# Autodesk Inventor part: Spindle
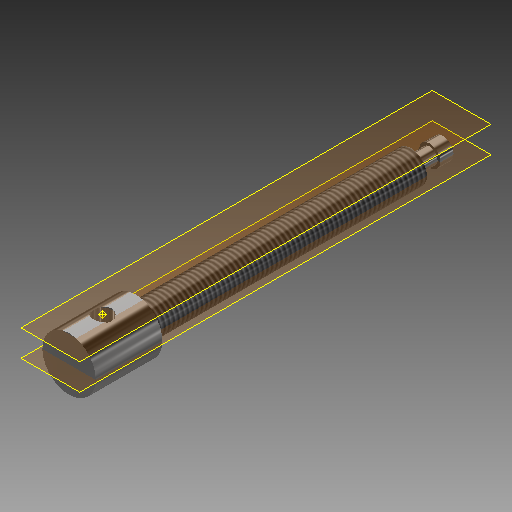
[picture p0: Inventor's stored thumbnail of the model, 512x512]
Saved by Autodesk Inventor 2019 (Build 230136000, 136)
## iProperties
Created: 2011-02
Part Number: Spindle
Material: Generic
Document SubType Name: Modeling
Designer: landrews
Density: 1 g/cm^3
Appearance: Knurled 45
Mass: 19.1947 g
Surface Area: 67.311 cm^2
Volume: 19.1947 cm^3
Author: landrews
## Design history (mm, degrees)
sketch "Sketch1"
  geometry: L1 (3, 5)-(4, 5); L2 (4, 5)-(4, 0); L3 (4, 0)-(0, 0); L4 (6, 115)-(6, 15); L5 (10, 115)-(6, 115); L6 (0, 140)-(10, 140); L7 (10, 140)-(10, 115); L8 (0, 168)-(0, -28) reference; L9 (-2, 0)-(12, 0) reference; L10 (3, 5)-(3, 15); L11 (3, 15)-(6, 15); L12 (0, 140)-(0, 0)
  constraints: 20 end point, 5 parallel, 3 perpendicular, 2 point on line, 1 collinear
  dimensions: "d4" = 25 distance between parallel lines of L6 L5; "d8" = 5 distance between parallel lines of L3 L1; "d9" = 140 distance between parallel lines of L9 L6; "d12" = 15 distance from line of L9 L4.end; "d15" = 12 diameter of L4 L12; "d16" = 6 diameter of L10 L8; "d17" = 8 diameter of L2 L8; "d18" = 20 diameter of L7 L12
revolve "Revolution1" sketch "Sketch1" stored, may be unused: angle "d19" = 90 deg
workplane "Work Plane1"
sketch "Sketch2"
  geometry: L1 (0, -155.5)-(0, 40.5) reference; L2 (-10, 12.5)-(10, 12.5) reference; 2 further points
  constraints: 1 point on line
  dimensions: "d20" = 12.5 distance from line of L2 point (0, 0)
hole "Hole1" sketch "Sketch2" at (0, 0) diameter "d21" = 7; stored, may be unused: countersink angle "d25" = 90 deg, drill point angle "d27" = 118 deg; dims "d22" = 6, "d23" = 4, "d24" = 2, "d26" = 8
thread "Thread1" dims "d28" = 10, "d29" = 0
workplane "Work Plane3"
  workplane "Work Plane2"
node "Direct Edit1"
body "Solid1"
node "Projected Loop1"
workpoint "Work Point1"
move_body "Move1" dims "d35" = 3
other parameters: "d30" = 0, "d33" = 0, "d34" = 0
